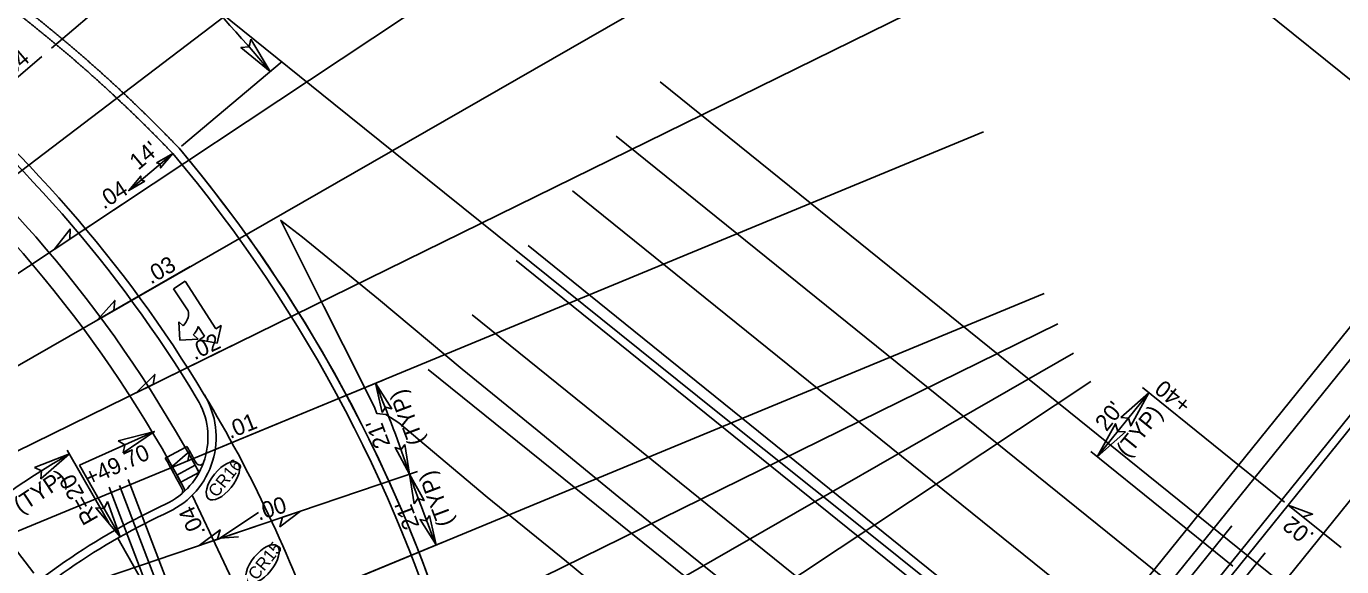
# Model space of a CAD drawing. Extents: x 1486489 to 1490134, y 497089 to 500876.
# Drawn here: x 1488524.4 to 1488844.3, y 499245.3 to 499376.7 of the extents above; entities that cross this region are included whole.
import ezdxf

# ---------------------------------------------------------------- set-up
doc = ezdxf.new("R2010")
doc.units = 0
for name, color, linetype in [('DEV PRELIMINARY STAMP CELL', 7, 'Continuous'), ('Gray Area Fill Shapes', 7, 'Continuous'), ('Old_Level_9', 7, 'Continuous'), ('Pattern 5', 7, 'Continuous'), ('Prop DSN Text', 7, 'Continuous'), ('Prop Guardrail', 7, 'Continuous'), ('Prop Horizontal Alignment Station Label', 7, 'Continuous'), ('Prop North Arrow NAD83 for Plan Sheets CELL', 7, 'Continuous'), ('Prop Rem of Exist Asph Pvmt', 7, 'Continuous'), ('Prop Text', 7, 'Continuous'), ('Prop WCC CELL', 7, 'Continuous'), ('Scratch_Level_0', 7, 'Continuous'), ('Scratch_Level_5', 7, 'Continuous'), ('Sheet Block Revision CELL', 7, 'Continuous'), ('Sheet Block Title CELL', 7, 'Continuous'), ('Sheet Cutting Line CELL', 7, 'Continuous'), ('Sheet Data Field CELL', 7, 'Continuous'), ('Sheet Plan CELL', 7, 'Continuous'), ('Sheet Plot Border Inside CELL', 7, 'Continuous'), ('Sheet Plot Border Outside CELL', 7, 'Continuous'), ('Sheet Sticker Exception Certification CELL', 7, 'Continuous')]:
    doc.layers.add(name, color=color, linetype=linetype)

msp = doc.modelspace()

# ---------------------------------------------------------------- linework, layer by layer
at = {"layer": 'DEV PRELIMINARY STAMP CELL'}
for p, q in [((1488784.87, 499271.99), (1488797.42, 499287.56)), ((1488830.4, 499260.96), (1488795.86, 499288.81)), ((1488534.38, 499273.57), (1488544.47, 499255.91)), ((1488817.85, 499245.39), (1488783.31, 499273.25)), ((1488526.22, 499243.66), (1488506.63, 499269.31)), ((1488575.18, 499240.55), (1488564.77, 499262.63)), ((1488844.13, 499249.89), (1488831.28, 499260.25)), ((1488546.63, 499252.2), (1488557.55, 499233.1))]:
    msp.add_line(p, q, dxfattribs=at)
for points in [[(1488790.56, 499281.53), (1488797.42, 499287.56), (1488792.98, 499279.51), (1488792.46, 499281.41)], [(1488791.72, 499278.02), (1488784.87, 499271.99), (1488789.3, 499280.04), (1488789.82, 499278.14)], [(1488526.38, 499269.37), (1488534.89, 499272.67), (1488527.96, 499266.64), (1488528.12, 499268.61)], [(1488831.28, 499260.25), (1488837.21, 499258.04), (1488834.88, 499257.35)]]:
    msp.add_lwpolyline(points, close=True, dxfattribs=at)
msp.add_arc((1488629.33, 499107.41), 190.34, 119.7468, 127.1377, dxfattribs=at)
at = {"layer": 'Old_Level_9'}
msp.add_lwpolyline([(1488890.07, 499123.82), (1488841.68, 499162.79), (1488822.88, 499177.94), (1488795.51, 499200.11), (1488763.62, 499225.91), (1488727.57, 499254.8), (1488692.17, 499283.06), (1488664.12, 499305.6), (1488617.82, 499342.84), (1488599.16, 499357.84), (1488532.76, 499411.39), (1488485.03, 499449.93), (1488450.03, 499478.08), (1488423.37, 499499.63), (1488397.39, 499520.51), (1488361.21, 499549.74)], dxfattribs=at)
at = {"layer": 'Pattern 5'}
for p, q in [((1488565.46, 499269.91), (1488561.05, 499267.54)), ((1488566.4, 499268.15), (1488565.46, 499269.91)), ((1488561.05, 499267.54), (1488562, 499265.78)), ((1488562, 499265.78), (1488566.4, 499268.15))]:
    msp.add_line(p, q, dxfattribs=at)
msp.add_lwpolyline([(1488565.46, 499269.91), (1488565.46, 499269.91)], dxfattribs=at)
at = {"layer": 'Prop DSN Text'}
for p, q in [((1488371.47, 499226.15), (1488689.82, 499468.34)), ((1488709.47, 499440.7), (1488376.15, 499219.56)), ((1488380.4, 499212.69), (1488727.3, 499411.84)), ((1488743.22, 499381.9), (1488384.19, 499205.56)), ((1488387.51, 499198.2), (1488757.19, 499350.99)), ((1488402.29, 499158.9), (1488771.96, 499311.68)), ((1488775.29, 499304.32), (1488416.25, 499127.99)), ((1488432.18, 499098.05), (1488779.08, 499297.19)), ((1488783.32, 499290.32), (1488450, 499069.19)), ((1488591.1, 499258.8), (1488390.36, 499190.64)), ((1488566.47, 498943.86), (1488817.57, 499255.22))]:
    msp.add_line(p, q, dxfattribs=at)
at = {"layer": 'Prop Guardrail'}
msp.add_arc((1488292.94, 499121.08), 351, 19.0041, 40.0716, dxfattribs=at)
msp.add_spline([(1488561.54, 499347.04), (1488560.36, 499348.26), (1488559.77, 499348.88), (1488559.18, 499349.49), (1488558.58, 499350.09), (1488557.99, 499350.7), (1488557.39, 499351.31), (1488556.79, 499351.91), (1488556.19, 499352.51), (1488555.59, 499353.11), (1488554.99, 499353.71), (1488554.38, 499354.31), (1488553.78, 499354.91), (1488553.17, 499355.5), (1488552.56, 499356.09), (1488551.95, 499356.68), (1488551.34, 499357.27), (1488550.73, 499357.86), (1488550.12, 499358.45), (1488549.5, 499359.03), (1488548.89, 499359.62), (1488548.27, 499360.2), (1488547.65, 499360.78), (1488547.03, 499361.36), (1488546.41, 499361.94), (1488545.78, 499362.51), (1488545.16, 499363.08), (1488544.53, 499363.66), (1488543.91, 499364.23), (1488543.28, 499364.8), (1488542.65, 499365.36), (1488542.02, 499365.93), (1488541.39, 499366.49), (1488540.76, 499367.06), (1488540.12, 499367.62), (1488539.49, 499368.18), (1488538.85, 499368.73), (1488538.21, 499369.29), (1488537.57, 499369.84), (1488536.93, 499370.4), (1488536.29, 499370.95), (1488535.65, 499371.5), (1488535, 499372.05), (1488534.36, 499372.59), (1488533.71, 499373.14), (1488533.06, 499373.68), (1488532.41, 499374.22), (1488531.76, 499374.76), (1488531.11, 499375.3), (1488530.46, 499375.83), (1488529.8, 499376.37), (1488529.15, 499376.9), (1488528.49, 499377.43), (1488527.83, 499377.96), (1488527.17, 499378.49), (1488526.51, 499379.02), (1488525.85, 499379.54), (1488525.19, 499380.06), (1488524.53, 499380.58), (1488523.86, 499381.1), (1488523.2, 499381.62), (1488522.53, 499382.14), (1488521.86, 499382.65), (1488521.19, 499383.16), (1488520.52, 499383.67), (1488519.85, 499384.18), (1488519.18, 499384.69), (1488518.5, 499385.2), (1488517.83, 499385.7), (1488517.15, 499386.2), (1488516.48, 499386.7), (1488515.8, 499387.2), (1488515.12, 499387.7), (1488514.44, 499388.19)], degree=3, dxfattribs=at)
at = {"layer": 'Prop Horizontal Alignment Station Label'}
for p, q in [((1488797.24, 499242.74), (1488875.71, 499340.04)), ((1488801.14, 499239.6), (1488864.05, 499317.61)), ((1488563.02, 499274.28), (1488558.62, 499271.91)), ((1488565.46, 499269.91), (1488561.05, 499267.54)), ((1488566.4, 499268.15), (1488562, 499265.78))]:
    msp.add_line(p, q, dxfattribs=at)
for radius, start in [(310.5, 28.2711), (305.5, 27.8434)]:
    msp.add_arc((1488292.94, 499121.08), radius, start, 51.1887, dxfattribs=at)
at = {"layer": 'Prop North Arrow NAD83 for Plan Sheets CELL'}
for p, q in [((1488563.02, 499274.28), (1488563.45, 499274.52)), ((1488558.62, 499271.91), (1488558.18, 499271.66))]:
    msp.add_line(p, q, dxfattribs=at)
for centre, radius, start, end in [((1488292.94, 499121.08), 311, 28.7133, 29.5629), ((1488292.94, 499121.08), 305, 27.967, 29.5841), ((1488566.58, 499270.98), 1, 208.7133, 340.2344), ((1488561.44, 499263.65), 1, 309.7122, 27.967)]:
    msp.add_arc(centre, radius, start, end, dxfattribs=at)
at = {"layer": 'Prop Rem of Exist Asph Pvmt'}
for points in [[(1488755.4, 499195.95), (1488744.07, 499202.68), (1488725.99, 499215.74), (1488710.36, 499228.49), (1488687.96, 499246.41), (1488668.5, 499262.14), (1488648.61, 499278.49), (1488630.4, 499293.26), (1488610.04, 499310.33), (1488591.6, 499325.39), (1488586.28, 499329.49), (1488591.25, 499319.52)], [(1488591.25, 499319.52), (1488596.78, 499308.53), (1488601.49, 499299.18), (1488609.01, 499284.22)], [(1488609.01, 499284.22), (1488609.63, 499282.52), (1488611.82, 499282.27), (1488614.97, 499280.23), (1488636.47, 499262.18), (1488655.78, 499246.53), (1488675.03, 499230.53), (1488696.14, 499213.29), (1488713.83, 499198.84), (1488732.27, 499185.48), (1488742.82, 499178.43)]]:
    msp.add_lwpolyline(points, dxfattribs=at)
at = {"layer": 'Prop Text'}
for p, q in [((1488566.03, 499222.24), (1488549.2, 499266.45)), ((1488544.56, 499264.58), (1488561.41, 499220.33))]:
    msp.add_line(p, q, dxfattribs=at)
at = {"layer": 'Prop WCC CELL'}
for centre in [(1488572.22, 499266.15), (1488581.86, 499245.95)]:
    msp.add_ellipse(centre, major_axis=(3.52, 4.36), ratio=0.462467, dxfattribs=at)
at = {"layer": 'Scratch_Level_0'}
for p, q in [((1488555.57, 499278.14), (1488537.34, 499269.93)), ((1488547.19, 499252.52), (1488537.34, 499269.93)), ((1488563.56, 499221.7), (1488547.08, 499265))]:
    msp.add_line(p, q, dxfattribs=at)
for points in [[(1488546.73, 499275.85), (1488555.57, 499278.14), (1488547.98, 499272.96), (1488548.37, 499274.89)], [(1488544.11, 499261.12), (1488547.19, 499252.52), (1488541.34, 499259.61), (1488543.3, 499259.4)]]:
    msp.add_lwpolyline(points, close=True, dxfattribs=at)
at = {"layer": 'Scratch_Level_5'}
for p, q in [((1488794.57, 499217.92), (1488886.22, 499331.56)), ((1488558.25, 499260.44), (1488557.05, 499259.88))]:
    msp.add_line(p, q, dxfattribs=at)
for centre, radius, start, end in [((1488292.94, 499121.08), 319, 31.1368, 51.1887), ((1488292.94, 499121.08), 351, 15.2846, 40.0716), ((1488550.58, 499276.73), 18, 295.2255, 31.1368), ((1488626.52, 499112.42), 163, 115.2255, 135.4445)]:
    msp.add_arc(centre, radius, start, end, dxfattribs=at)
msp.add_spline([(1488514.44, 499388.19), (1488515.12, 499387.7), (1488515.8, 499387.2), (1488516.48, 499386.7), (1488517.15, 499386.2), (1488517.83, 499385.7), (1488518.5, 499385.2), (1488519.18, 499384.69), (1488519.85, 499384.18), (1488520.52, 499383.67), (1488521.19, 499383.16), (1488521.86, 499382.65), (1488522.53, 499382.14), (1488523.2, 499381.62), (1488523.86, 499381.1), (1488524.53, 499380.58), (1488525.19, 499380.06), (1488525.85, 499379.54), (1488526.51, 499379.02), (1488527.17, 499378.49), (1488527.83, 499377.96), (1488528.49, 499377.43), (1488529.15, 499376.9), (1488529.8, 499376.37), (1488530.46, 499375.83), (1488531.11, 499375.3), (1488531.76, 499374.76), (1488532.41, 499374.22), (1488533.06, 499373.68), (1488533.71, 499373.14), (1488534.36, 499372.59), (1488535, 499372.05), (1488535.65, 499371.5), (1488536.29, 499370.95), (1488536.93, 499370.4), (1488537.57, 499369.84), (1488538.21, 499369.29), (1488538.85, 499368.73), (1488539.49, 499368.18), (1488540.12, 499367.62), (1488540.76, 499367.06), (1488541.39, 499366.49), (1488542.02, 499365.93), (1488542.65, 499365.36), (1488543.28, 499364.8), (1488543.91, 499364.23), (1488544.53, 499363.66), (1488545.16, 499363.08), (1488545.78, 499362.51), (1488546.41, 499361.94), (1488547.03, 499361.36), (1488547.65, 499360.78), (1488548.27, 499360.2), (1488548.89, 499359.62), (1488549.5, 499359.03), (1488550.12, 499358.45), (1488550.73, 499357.86), (1488551.34, 499357.27), (1488551.95, 499356.68), (1488552.56, 499356.09), (1488553.17, 499355.5), (1488553.78, 499354.91), (1488554.38, 499354.31), (1488554.99, 499353.71), (1488555.59, 499353.11), (1488556.19, 499352.51), (1488556.79, 499351.91), (1488557.39, 499351.31), (1488557.99, 499350.7), (1488558.58, 499350.09), (1488559.18, 499349.49), (1488559.77, 499348.88), (1488560.36, 499348.26), (1488561.54, 499347.04)], degree=3, dxfattribs=at)
at = {"layer": 'Sheet Block Revision CELL'}
msp.add_lwpolyline([(1488580.84, 499258.46), (1488571.46, 499252.2), (1488576.02, 499252.5)], dxfattribs=at)
at = {"layer": 'Sheet Block Title CELL'}
msp.add_line((1488809.08, 499215.2), (1488874.37, 499296.16), dxfattribs=at)
msp.add_arc((1488292.94, 499121.08), 321, 19.3141, 31.1366, dxfattribs=at)
at = {"layer": 'Sheet Cutting Line CELL'}
for p, q in [((1488586.6, 499368.11), (1488562.16, 499347.56)), ((1488549.3, 499336.74), (1488560.01, 499345.75))]:
    msp.add_line(p, q, dxfattribs=at)
msp.add_arc((1488292.94, 499121.08), 380, 40.0716, 50.3336, dxfattribs=at)
at = {"layer": 'Sheet Data Field CELL'}
for p, q in [((1488530.49, 499371.32), (1488558.62, 499395.36)), ((1488508.44, 499352.48), (1488528.21, 499369.37)), ((1488531.14, 499322.39), (1488552.81, 499336.76)), ((1488541.71, 499305.3), (1488564.25, 499318.24)), ((1488551.14, 499287.56), (1488574.48, 499299.02)), ((1488583.44, 499279.18), (1488611.16, 499290.64)), ((1488559.41, 499269.25), (1488583.44, 499279.18)), ((1488591.1, 499258.8), (1488619.51, 499268.44)), ((1488566.48, 499250.44), (1488591.1, 499258.8)), ((1488625.94, 499251.33), (1488598.22, 499239.87))]:
    msp.add_line(p, q, dxfattribs=at)
for points in [[(1488531.14, 499322.39), (1488535.04, 499327.37), (1488535, 499324.95)], [(1488541.71, 499305.3), (1488545.91, 499310.02), (1488545.72, 499307.6)], [(1488551.14, 499287.56), (1488555.64, 499292), (1488555.29, 499289.6)], [(1488610.92, 499282.75), (1488609.32, 499289.87), (1488613.26, 499283.67), (1488611.73, 499284.03)], [(1488559.41, 499269.25), (1488564.19, 499273.39), (1488563.69, 499271.01)], [(1488616.48, 499275.01), (1488617.62, 499267.8), (1488614.08, 499274.24), (1488615.58, 499273.78)], [(1488618.76, 499260.58), (1488617.62, 499267.8), (1488621.16, 499261.35), (1488619.65, 499261.81)], [(1488591.1, 499258.8), (1488586.06, 499254.97), (1488586.72, 499257.31)], [(1488622.49, 499257.69), (1488624.09, 499250.57), (1488620.15, 499256.77), (1488621.68, 499256.41)], [(1488566.48, 499250.44), (1488571.52, 499254.26), (1488570.86, 499251.93)]]:
    msp.add_lwpolyline(points, close=True, dxfattribs=at)
for centre, radius, start, end in [((1488271.99, 499150.46), 365, 18.752, 22.4548), ((1488887.49, 499359.42), 285, 198.752, 202.4537)]:
    msp.add_arc(centre, radius, start, end, dxfattribs=at)
at = {"layer": 'Sheet Plan CELL'}
for p, q in [((1488744.94, 499445.5), (1489056.31, 499194.4)), ((1488989.91, 499112.07), (1488678.54, 499363.17)), ((1488667.87, 499349.94), (1488979.24, 499098.84)), ((1488968.56, 499085.6), (1488657.2, 499336.7)), ((1488646.42, 499323.34), (1488957.79, 499072.24)), ((1488954.87, 499068.62), (1488643.5, 499319.72)), ((1488632.83, 499306.48), (1488944.2, 499055.38)), ((1488933.52, 499042.15), (1488622.16, 499293.25)), ((1488574.59, 498937.3), (1488825.69, 499248.67))]:
    msp.add_line(p, q, dxfattribs=at)
at = {"layer": 'Sheet Plot Border Inside CELL'}
for p, q in [((1488560.23, 499312.86), (1488563, 499314.66)), ((1488563, 499314.66), (1488570.52, 499303.09)), ((1488563.75, 499307.45), (1488560.23, 499312.86)), ((1488561.73, 499300.36), (1488561.48, 499304.79)), ((1488561.48, 499304.79), (1488562.58, 499303.83)), ((1488567.75, 499301.29), (1488566.2, 499303.68)), ((1488570.52, 499303.09), (1488571.77, 499303.9)), ((1488571.77, 499303.9), (1488570.82, 499299.59)), ((1488566.16, 499300.61), (1488561.73, 499300.36)), ((1488565.03, 499301.61), (1488566.16, 499300.61)), ((1488566.49, 499300.47), (1488567.75, 499301.29)), ((1488570.82, 499299.59), (1488566.49, 499300.47))]:
    msp.add_line(p, q, dxfattribs=at)
for centre, radius, start, end in [((1488559.46, 499306.99), 4.43, 314.704, 345.5576), ((1488561.35, 499306.66), 2.52, 342.0675, 18.3795), ((1488561.91, 499304.78), 4.43, 314.5852, 345.4638)]:
    msp.add_arc(centre, radius, start, end, dxfattribs=at)
at = {"layer": 'Sheet Plot Border Outside CELL'}
for points in [[(1488579.03, 499373.53), (1488583.73, 499365.71), (1488576.61, 499371.51), (1488578.57, 499371.69)], [(1488556.07, 499343.45), (1488560.01, 499345.75), (1488557.06, 499342.22), (1488556.99, 499343.21)], [(1488553.24, 499339.04), (1488549.3, 499336.74), (1488552.25, 499340.26), (1488552.32, 499339.28)]]:
    msp.add_lwpolyline(points, close=True, dxfattribs=at)
at = {"layer": 'Sheet Sticker Exception Certification CELL'}
for p, q in [((1488732.3, 499137.52), (1488887.78, 499330.31)), ((1488559.1, 499258.63), (1488557.9, 499258.07))]:
    msp.add_line(p, q, dxfattribs=at)
for centre, radius, start, end in [((1488292.94, 499121.08), 321, 31.1368, 51.1887), ((1488292.94, 499121.08), 349, 15.2846, 40.0716), ((1488550.58, 499276.73), 20, 295.2255, 31.1368), ((1488626.52, 499112.42), 161, 115.2255, 135.4445)]:
    msp.add_arc(centre, radius, start, end, dxfattribs=at)
msp.add_spline([(1488513.16, 499386.65), (1488513.84, 499386.16), (1488514.51, 499385.67), (1488515.19, 499385.17), (1488515.86, 499384.68), (1488516.53, 499384.18), (1488517.21, 499383.68), (1488517.88, 499383.17), (1488518.55, 499382.67), (1488519.21, 499382.16), (1488519.88, 499381.66), (1488520.55, 499381.15), (1488521.21, 499380.63), (1488521.87, 499380.12), (1488522.54, 499379.61), (1488523.2, 499379.09), (1488523.86, 499378.57), (1488524.51, 499378.05), (1488525.17, 499377.53), (1488525.83, 499377.01), (1488526.48, 499376.49), (1488527.14, 499375.96), (1488527.79, 499375.43), (1488528.44, 499374.9), (1488529.09, 499374.37), (1488529.74, 499373.84), (1488530.39, 499373.3), (1488531.04, 499372.77), (1488531.68, 499372.23), (1488532.33, 499371.69), (1488532.97, 499371.15), (1488533.61, 499370.61), (1488534.25, 499370.06), (1488534.89, 499369.52), (1488535.53, 499368.97), (1488536.17, 499368.42), (1488536.8, 499367.87), (1488537.44, 499367.32), (1488538.07, 499366.76), (1488538.71, 499366.2), (1488539.34, 499365.65), (1488539.97, 499365.09), (1488540.59, 499364.53), (1488541.22, 499363.97), (1488541.85, 499363.4), (1488542.47, 499362.84), (1488543.1, 499362.27), (1488543.72, 499361.7), (1488544.34, 499361.13), (1488544.96, 499360.56), (1488545.58, 499359.98), (1488546.19, 499359.41), (1488546.81, 499358.83), (1488547.42, 499358.25), (1488548.03, 499357.67), (1488548.65, 499357.09), (1488549.26, 499356.51), (1488549.87, 499355.93), (1488550.47, 499355.34), (1488551.08, 499354.75), (1488551.68, 499354.16), (1488552.29, 499353.57), (1488552.89, 499352.98), (1488553.49, 499352.38), (1488554.09, 499351.79), (1488554.69, 499351.19), (1488555.29, 499350.59), (1488555.88, 499349.99), (1488556.48, 499349.39), (1488557.07, 499348.79), (1488557.66, 499348.18), (1488558.25, 499347.58), (1488558.84, 499346.97), (1488560.01, 499345.75)], degree=3, dxfattribs=at)

# ---------------------------------------------------------------- texts
at = {"layer": 'DEV PRELIMINARY STAMP CELL'}
for s, rotation, p in [("20'", 51.1156, (1488787.1, 499277.95)), ('(TYP)', 51.1156, (1488792.24, 499271.57)), ('(TYP)', 33.5665, (1488523.01, 499258.09))]:
    msp.add_text(s, height=4, rotation=rotation, dxfattribs=at).set_placement(p)
at = {"layer": 'Gray Area Fill Shapes'}
for s, rotation, p in [('+40', 141.1755, (1488808.05, 499285.26)), ('.04', 115.2255, (1488568.07, 499253.67)), ('.02', 141.1755, (1488837.87, 499253.13))]:
    msp.add_text(s, height=4, rotation=rotation, dxfattribs=at).set_placement(p)
at = {"layer": 'Prop WCC CELL'}
for s, p in [('CR16', (1488570.69, 499261.9)), ('CR15', (1488580.38, 499241.76))]:
    msp.add_text(s, height=3, rotation=51.1156, dxfattribs=at).set_placement(p)
at = {"layer": 'Scratch_Level_0'}
for s, rotation, p in [('+49.70', 24.3529, (1488539.73, 499264.79)), ("R=20'", 119.5183, (1488542.05, 499256.92))]:
    msp.add_text(s, height=4, rotation=rotation, dxfattribs=at).set_placement(p)
at = {"layer": 'Sheet Cutting Line CELL'}
msp.add_text("14'", height=4, rotation=40.0716, dxfattribs=at).set_placement((1488551.61, 499341.52))
at = {"layer": 'Sheet Data Field CELL'}
for s, rotation, p in [('.04', 40.5109, (1488519.89, 499363.51)), ('.04', 33.0245, (1488543.27, 499332.04)), ('.03', 30.0711, (1488554.72, 499313.84)), ('.02', 25.4173, (1488565.32, 499295.42)), ('(TYP)', 110.6032, (1488621.27, 499275.68)), ('.01', 21.7152, (1488573.98, 499276.31)), ("21'", 110.6032, (1488613, 499274.95)), ('(TYP)', 110.6032, (1488628.34, 499255.91)), ('.00', 17.3742, (1488580.95, 499256.44)), ("21'", 110.6032, (1488620.07, 499255.17))]:
    msp.add_text(s, height=4, rotation=rotation, dxfattribs=at).set_placement(p)

doc.saveas('drawing.dxf')
